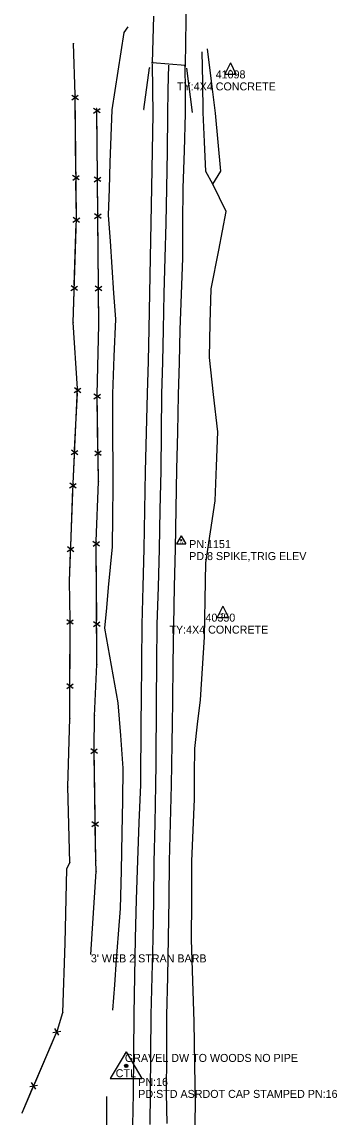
# Model space of a CAD drawing. Extents: x 1445297 to 1476720, y 2042269 to 2057889.
# Drawn here: x 1476144 to 1476341, y 2054738 to 2055423 of the extents above; entities that cross this region are included whole.
import ezdxf

# ---------------------------------------------------------------- set-up
doc = ezdxf.new("R2010")
doc.units = 0
for name, color, linetype in [('S_BRIDGE', 7, 'Continuous'), ('S_DITCHLINE', 7, 'Continuous'), ('S_EDGE_PAVEMENT', 7, 'Continuous'), ('S_EXIST_ROW', 7, 'Continuous'), ('S_EXIST_ROW_ANNOT', 7, 'Continuous'), ('S_FENCE', 7, 'Continuous'), ('S_FENCE_ANNOT', 7, 'Continuous'), ('S_GUARDRAIL', 7, 'Continuous'), ('S_MSC_PT_SYM', 7, 'Continuous'), ('S_PAVEMENT_CROWN', 7, 'Continuous'), ('S_PRIMARY_CTL', 7, 'Continuous'), ('S_PRIMARY_CTL_ANNOT', 7, 'Continuous'), ('S_RDW_PT_SYM', 7, 'Continuous'), ('S_SECONDARY_CTL', 7, 'Continuous'), ('S_SECONDARY_CTL_ANNOT', 7, 'Continuous'), ('S_STR_PT_SYM', 7, 'Continuous'), ('S_SURVEY_TEXT_ANNOT', 7, 'Continuous')]:
    doc.layers.add(name, color=color, linetype=linetype)

msp = doc.modelspace()

# ---------------------------------------------------------------- linework, layer by layer
at = {"layer": 'S_BRIDGE'}
for p, q in [((1476247.02, 2055440.81), (1476246.16, 2055395.44)), ((1476225.79, 2055397.26), (1476226.59, 2055426.32)), ((1476246.16, 2055395.44), (1476225.79, 2055397.26))]:
    msp.add_line(p, q, dxfattribs=at)
at = {"layer": 'S_DITCHLINE'}
for points in [[(1476201, 2054805.2), (1476202.23, 2054821.06), (1476203.47, 2054836.92), (1476204.7, 2054852.77), (1476205.93, 2054868.63), (1476206.4, 2054892.32), (1476206.86, 2054916.02), (1476207.23, 2054936.26), (1476207.6, 2054956.5), (1476206.03, 2054976.84), (1476204.47, 2054997.17), (1476200.28, 2055020.49), (1476196.1, 2055043.8), (1476197.27, 2055056.53), (1476198.44, 2055069.26), (1476199.61, 2055081.99), (1476200.78, 2055094.72), (1476201.04, 2055113.61), (1476201.3, 2055132.51), (1476201.24, 2055146.94), (1476201.18, 2055161.38), (1476201.12, 2055175.82), (1476201.06, 2055190.26), (1476201.98, 2055213.68), (1476202.9, 2055237.09), (1476201.79, 2055253.31), (1476200.68, 2055269.53), (1476199.56, 2055285.75), (1476198.45, 2055301.96), (1476198.98, 2055318.41), (1476199.5, 2055334.85), (1476200.03, 2055351.3), (1476200.56, 2055367.75), (1476204.33, 2055391.96), (1476208.11, 2055416.17), (1476210.63, 2055419.7)], [(1476252.3, 2054729.43), (1476252.65, 2054745), (1476252.47, 2054758.22), (1476252.3, 2054771.45), (1476252.13, 2054784.67), (1476251.95, 2054797.89), (1476251.51, 2054810.74), (1476251.06, 2054823.59), (1476250.62, 2054836.44), (1476250.17, 2054849.29), (1476250.32, 2054873.74), (1476250.48, 2054898.19), (1476251.24, 2054917.57), (1476252, 2054936.94), (1476252.11, 2054952.82), (1476252.22, 2054968.69), (1476254.04, 2054983.85), (1476255.87, 2054999.01), (1476257.11, 2055018.63), (1476258.35, 2055038.25), (1476258.8, 2055061.52), (1476259.25, 2055084.79), (1476262.13, 2055104.11), (1476265.01, 2055123.44), (1476265.87, 2055145.03), (1476266.73, 2055166.61), (1476264.05, 2055189.83), (1476261.37, 2055213.04), (1476261.96, 2055234.47), (1476262.55, 2055255.9), (1476267.2, 2055280.06), (1476271.86, 2055304.23), (1476263.53, 2055321.44), (1476259.16, 2055329.3), (1476258.37, 2055347.74), (1476257.58, 2055366.18), (1476257.21, 2055385.09), (1476256.83, 2055404.01)], [(1476263.53, 2055321.44), (1476268.63, 2055329.52), (1476266.91, 2055347.57), (1476265.19, 2055365.63), (1476262.72, 2055385.73), (1476260.25, 2055405.83)], [(1476197.26, 2054725.7), (1476197.33, 2054738.49), (1476197.4, 2054751.28)]]:
    msp.add_lwpolyline(points, dxfattribs=at)
at = {"layer": 'S_EDGE_PAVEMENT'}
for points in [[(1476213.56, 2054733.17), (1476213.95, 2054753.04), (1476214.18, 2054777.82), (1476214.4, 2054802.6), (1476214.8, 2054826.33), (1476215.19, 2054850.05), (1476215.94, 2054874.34), (1476216.69, 2054898.63), (1476217.6, 2054922.36), (1476218.51, 2054946.09), (1476218.63, 2054959.26), (1476218.75, 2054972.43), (1476218.87, 2054985.59), (1476218.99, 2054998.76), (1476219.22, 2055022.5), (1476219.45, 2055046.25), (1476220.09, 2055069.87), (1476220.73, 2055093.49), (1476221.13, 2055117.66), (1476221.53, 2055141.83), (1476222.13, 2055166.13), (1476222.74, 2055190.44), (1476223.26, 2055210.74), (1476223.77, 2055231.04), (1476224.21, 2055253.15), (1476224.65, 2055275.26), (1476225.05, 2055297.22), (1476225.45, 2055319.18), (1476225.88, 2055342.1), (1476226.32, 2055365.01), (1476226.04, 2055380.65), (1476225.76, 2055396.29)], [(1476234.92, 2054734.25), (1476234.56, 2054753.27), (1476234.73, 2054777.57), (1476234.9, 2054801.86), (1476235.36, 2054826.08), (1476235.82, 2054850.3), (1476236.19, 2054874.28), (1476236.56, 2054898.27), (1476237.18, 2054922), (1476237.79, 2054945.73), (1476237.98, 2054958.72), (1476238.16, 2054971.7), (1476238.34, 2054984.68), (1476238.52, 2054997.67), (1476238.8, 2055021.72), (1476239.08, 2055045.77), (1476239.6, 2055069.72), (1476240.13, 2055093.67), (1476240.62, 2055118.48), (1476241.12, 2055143.29), (1476241.64, 2055166.45), (1476242.16, 2055189.61), (1476242.7, 2055209.96), (1476243.23, 2055230.31), (1476243.98, 2055252.69), (1476244.73, 2055275.07), (1476244.87, 2055297.04), (1476245.02, 2055319.02), (1476245.79, 2055342.27), (1476246.55, 2055365.52), (1476246.38, 2055380.12), (1476246.22, 2055394.73)]]:
    msp.add_lwpolyline(points, dxfattribs=at)
at = {"layer": 'S_EXIST_ROW'}
for p, q in [((1476274.51, 2055397.17), (1476270.98, 2055390.08)), ((1476274.51, 2055397.17), (1476277.99, 2055390.08)), ((1476270.98, 2055390.08), (1476277.99, 2055390.08)), ((1476274.49, 2055392.45), (1476274.49, 2055392.45)), ((1476269.76, 2055057.71), (1476266.24, 2055050.62)), ((1476269.76, 2055057.71), (1476273.25, 2055050.62)), ((1476266.24, 2055050.62), (1476273.25, 2055050.62)), ((1476269.75, 2055052.98), (1476269.75, 2055052.98))]:
    msp.add_line(p, q, dxfattribs=at)
for centre, radius in [((1476274.49, 2055392.45), 0.12), ((1476274.49, 2055392.45), 0.06), ((1476269.75, 2055052.98), 0.12), ((1476269.75, 2055052.98), 0.06)]:
    msp.add_circle(centre, radius, dxfattribs=at)
at = {"layer": 'S_FENCE'}
for p, q in [((1476177.47, 2055377.08), (1476176.56, 2055409.33)), ((1476179.55, 2055374.04), (1476175.42, 2055376.86)), ((1476175.46, 2055373.99), (1476179.52, 2055376.91)), ((1476178.33, 2055300.34), (1476177.47, 2055377.08)), ((1476193.1, 2055365.85), (1476188.97, 2055368.67)), ((1476189, 2055365.81), (1476193.07, 2055368.72)), ((1476191.74, 2055302.89), (1476191.02, 2055368.66)), ((1476180.11, 2055323.97), (1476175.98, 2055326.79)), ((1476176.02, 2055323.92), (1476180.08, 2055326.83)), ((1476193.57, 2055322.94), (1476189.44, 2055325.76)), ((1476189.47, 2055322.89), (1476193.54, 2055325.8)), ((1476176.19, 2055297.58), (1476180.38, 2055300.32)), ((1476180.29, 2055297.45), (1476176.28, 2055300.45)), ((1476176.31, 2055235), (1476178.33, 2055300.34)), ((1476193.81, 2055300), (1476189.69, 2055302.83)), ((1476189.72, 2055299.96), (1476193.79, 2055302.87)), ((1476192.36, 2055233.5), (1476191.74, 2055302.89)), ((1476174.87, 2055254.95), (1476179.06, 2055257.69)), ((1476178.97, 2055254.82), (1476174.96, 2055257.82)), ((1476194.22, 2055254.73), (1476190.1, 2055257.56)), ((1476190.12, 2055254.69), (1476194.19, 2055257.59)), ((1476179.08, 2055193.74), (1476176.31, 2055235)), ((1476191.32, 2055189.9), (1476192.36, 2055233.5)), ((1476176.21, 2055134.24), (1476179.08, 2055193.74)), ((1476176.9, 2055191.14), (1476181.13, 2055193.81)), ((1476180.99, 2055190.95), (1476177.04, 2055194.01)), ((1476193.4, 2055187.33), (1476189.26, 2055190.14)), ((1476189.3, 2055187.28), (1476193.36, 2055190.2)), ((1476192.06, 2055135.4), (1476191.32, 2055189.9)), ((1476175.03, 2055152.32), (1476179.26, 2055154.98)), ((1476179.12, 2055152.12), (1476175.17, 2055155.18)), ((1476193.88, 2055151.77), (1476189.75, 2055154.59)), ((1476189.79, 2055151.72), (1476193.84, 2055154.64)), ((1476174.01, 2055073.26), (1476176.21, 2055134.24)), ((1476174.06, 2055131.58), (1476178.26, 2055134.3)), ((1476178.16, 2055131.43), (1476174.17, 2055134.45)), ((1476190.74, 2055098.18), (1476192.06, 2055135.4)), ((1476192.8, 2055095.12), (1476188.69, 2055097.96)), ((1476188.71, 2055095.1), (1476192.79, 2055097.98)), ((1476191.16, 2055021.29), (1476190.74, 2055098.18)), ((1476172.63, 2055091.8), (1476176.82, 2055094.51)), ((1476176.72, 2055091.65), (1476172.73, 2055094.66)), ((1476174.35, 2055049.05), (1476174.01, 2055073.26)), ((1476176.4, 2055046.32), (1476172.3, 2055049.15)), ((1476172.3, 2055046.33), (1476176.4, 2055049.15)), ((1476174.28, 2054987.57), (1476174.35, 2055049.05)), ((1476193.08, 2055044.96), (1476188.96, 2055047.8)), ((1476188.98, 2055044.94), (1476193.06, 2055047.82)), ((1476189.63, 2054989.2), (1476191.16, 2055021.29)), ((1476176.35, 2055006.21), (1476172.25, 2055009.04)), ((1476172.25, 2055006.22), (1476176.35, 2055009.04)), ((1476173, 2054944.65), (1476174.28, 2054987.57)), ((1476189.35, 2054968.52), (1476189.63, 2054989.2)), ((1476191.44, 2054965.63), (1476187.3, 2054968.44)), ((1476187.34, 2054965.57), (1476191.39, 2054968.5)), ((1476190.42, 2054898.61), (1476189.35, 2054968.52)), ((1476174.32, 2054897.52), (1476173, 2054944.65)), ((1476192.14, 2054920.02), (1476188, 2054922.82)), ((1476188.05, 2054919.96), (1476192.1, 2054922.89)), ((1476172.36, 2054893.51), (1476174.32, 2054897.52)), ((1476190.76, 2054891.75), (1476190.42, 2054898.61)), ((1476171.32, 2054847.03), (1476172.36, 2054893.51)), ((1476187.37, 2054840.04), (1476190.76, 2054891.75)), ((1476169.77, 2054803.8), (1476171.32, 2054847.03)), ((1476166.59, 2054792.73), (1476169.77, 2054803.8)), ((1476167.43, 2054789.5), (1476164.8, 2054793.75)), ((1476144.35, 2054741.03), (1476166.59, 2054792.73)), ((1476163.67, 2054791.12), (1476168.56, 2054792.13)), ((1476152.92, 2054755.77), (1476150.29, 2054760.02)), ((1476149.15, 2054757.39), (1476154.05, 2054758.4))]:
    msp.add_line(p, q, dxfattribs=at)
for points in [[(1476177.47, 2055377.08), (1476176.56, 2055409.33)], [(1476178.02, 2055327.65), (1476177.51, 2055373.17)], [(1476191.48, 2055326.3), (1476191.06, 2055365.31)], [(1476178.33, 2055300.34), (1476178.07, 2055323.1)], [(1476191.74, 2055302.89), (1476191.52, 2055322.4)], [(1476177.03, 2055258.26), (1476178.22, 2055297.01)], [(1476192.14, 2055258.2), (1476191.77, 2055299.36)], [(1476176.31, 2055235), (1476176.91, 2055254.38)], [(1476192.36, 2055233.5), (1476192.18, 2055254.08)], [(1476179.08, 2055193.74), (1476176.31, 2055235)], [(1476191.32, 2055189.9), (1476192.36, 2055233.5)], [(1476177.23, 2055155.41), (1476178.93, 2055190.71)], [(1476191.79, 2055154.8), (1476191.35, 2055187.12)], [(1476176.21, 2055134.24), (1476177.06, 2055151.88)], [(1476192.06, 2055135.4), (1476191.84, 2055151.56)], [(1476174.79, 2055094.96), (1476176.09, 2055131.13)], [(1476190.74, 2055098.18), (1476192.06, 2055135.4)], [(1476174.01, 2055073.26), (1476174.66, 2055091.35)], [(1476191.01, 2055048.66), (1476190.76, 2055094.26)], [(1476174.35, 2055049.05), (1476174.01, 2055073.26)], [(1476174.3, 2055009.45), (1476174.35, 2055045.91)], [(1476191.16, 2055021.29), (1476191.03, 2055044.1)], [(1476189.63, 2054989.2), (1476191.16, 2055021.29)], [(1476174.28, 2054987.57), (1476174.3, 2055005.81)], [(1476173, 2054944.65), (1476174.28, 2054987.57)], [(1476189.35, 2054968.52), (1476189.63, 2054989.2)], [(1476190.04, 2054923.49), (1476189.4, 2054964.96)], [(1476174.32, 2054897.52), (1476173, 2054944.65)], [(1476190.42, 2054898.61), (1476190.1, 2054919.35)], [(1476172.36, 2054893.51), (1476174.32, 2054897.52)], [(1476190.76, 2054891.75), (1476190.42, 2054898.61)], [(1476171.32, 2054847.03), (1476172.36, 2054893.51)], [(1476187.37, 2054840.04), (1476190.76, 2054891.75)], [(1476169.77, 2054803.8), (1476171.32, 2054847.03)], [(1476166.59, 2054792.73), (1476169.77, 2054803.8)], [(1476152.26, 2054759.43), (1476165.45, 2054790.09)], [(1476144.35, 2054741.03), (1476150.94, 2054756.36)]]:
    msp.add_lwpolyline(points, dxfattribs=at)
at = {"layer": 'S_GUARDRAIL'}
for p, q in [((1476220.54, 2055367.98), (1476223.91, 2055393.97)), ((1476250.86, 2055366.18), (1476247.3, 2055393.89))]:
    msp.add_line(p, q, dxfattribs=at)
at = {"layer": 'S_MSC_PT_SYM'}
for points in [[(1476176.56, 2055409.33), (1476176.56, 2055409.38), (1476176.56, 2055409.33), (1476176.51, 2055409.33), (1476176.56, 2055409.33), (1476176.56, 2055409.28), (1476176.56, 2055409.33), (1476176.61, 2055409.33)], [(1476177.47, 2055377.08), (1476177.47, 2055377.13), (1476177.47, 2055377.08), (1476177.42, 2055377.08), (1476177.47, 2055377.08), (1476177.47, 2055377.03), (1476177.47, 2055377.08), (1476177.52, 2055377.08)], [(1476191.02, 2055368.66), (1476191.02, 2055368.71), (1476191.02, 2055368.66), (1476190.97, 2055368.66), (1476191.02, 2055368.66), (1476191.02, 2055368.61), (1476191.02, 2055368.66), (1476191.07, 2055368.66)], [(1476178.33, 2055300.34), (1476178.33, 2055300.39), (1476178.33, 2055300.34), (1476178.28, 2055300.34), (1476178.33, 2055300.34), (1476178.33, 2055300.29), (1476178.33, 2055300.34), (1476178.38, 2055300.34)], [(1476191.74, 2055302.89), (1476191.74, 2055302.94), (1476191.74, 2055302.89), (1476191.69, 2055302.89), (1476191.74, 2055302.89), (1476191.74, 2055302.84), (1476191.74, 2055302.89), (1476191.79, 2055302.89)], [(1476176.31, 2055235), (1476176.31, 2055235.05), (1476176.31, 2055235), (1476176.26, 2055235), (1476176.31, 2055235), (1476176.31, 2055234.95), (1476176.31, 2055235), (1476176.36, 2055235)], [(1476192.36, 2055233.5), (1476192.36, 2055233.55), (1476192.36, 2055233.5), (1476192.31, 2055233.5), (1476192.36, 2055233.5), (1476192.36, 2055233.45), (1476192.36, 2055233.5), (1476192.41, 2055233.5)], [(1476179.08, 2055193.74), (1476179.08, 2055193.79), (1476179.08, 2055193.74), (1476179.03, 2055193.74), (1476179.08, 2055193.74), (1476179.08, 2055193.69), (1476179.08, 2055193.74), (1476179.13, 2055193.74)], [(1476191.32, 2055189.9), (1476191.32, 2055189.95), (1476191.32, 2055189.9), (1476191.27, 2055189.9), (1476191.32, 2055189.9), (1476191.32, 2055189.85), (1476191.32, 2055189.9), (1476191.37, 2055189.9)], [(1476176.21, 2055134.24), (1476176.21, 2055134.29), (1476176.21, 2055134.24), (1476176.16, 2055134.24), (1476176.21, 2055134.24), (1476176.21, 2055134.19), (1476176.21, 2055134.24), (1476176.26, 2055134.24)], [(1476192.06, 2055135.4), (1476192.06, 2055135.45), (1476192.06, 2055135.4), (1476192.01, 2055135.4), (1476192.06, 2055135.4), (1476192.06, 2055135.35), (1476192.06, 2055135.4), (1476192.11, 2055135.4)], [(1476190.74, 2055098.18), (1476190.74, 2055098.23), (1476190.74, 2055098.18), (1476190.69, 2055098.18), (1476190.74, 2055098.18), (1476190.74, 2055098.13), (1476190.74, 2055098.18), (1476190.79, 2055098.18)], [(1476174.01, 2055073.26), (1476174.01, 2055073.31), (1476174.01, 2055073.26), (1476173.96, 2055073.26), (1476174.01, 2055073.26), (1476174.01, 2055073.21), (1476174.01, 2055073.26), (1476174.06, 2055073.26)], [(1476174.35, 2055049.05), (1476174.35, 2055049.1), (1476174.35, 2055049.05), (1476174.3, 2055049.05), (1476174.35, 2055049.05), (1476174.35, 2055049), (1476174.35, 2055049.05), (1476174.4, 2055049.05)], [(1476191.16, 2055021.29), (1476191.16, 2055021.34), (1476191.16, 2055021.29), (1476191.11, 2055021.29), (1476191.16, 2055021.29), (1476191.16, 2055021.24), (1476191.16, 2055021.29), (1476191.21, 2055021.29)], [(1476174.28, 2054987.57), (1476174.28, 2054987.62), (1476174.28, 2054987.57), (1476174.23, 2054987.57), (1476174.28, 2054987.57), (1476174.28, 2054987.52), (1476174.28, 2054987.57), (1476174.33, 2054987.57)], [(1476189.63, 2054989.2), (1476189.63, 2054989.25), (1476189.63, 2054989.2), (1476189.58, 2054989.2), (1476189.63, 2054989.2), (1476189.63, 2054989.15), (1476189.63, 2054989.2), (1476189.68, 2054989.2)], [(1476189.35, 2054968.52), (1476189.35, 2054968.57), (1476189.35, 2054968.52), (1476189.3, 2054968.52), (1476189.35, 2054968.52), (1476189.35, 2054968.47), (1476189.35, 2054968.52), (1476189.4, 2054968.52)], [(1476173, 2054944.65), (1476173, 2054944.7), (1476173, 2054944.65), (1476172.95, 2054944.65), (1476173, 2054944.65), (1476173, 2054944.6), (1476173, 2054944.65), (1476173.05, 2054944.65)], [(1476174.32, 2054897.52), (1476174.32, 2054897.57), (1476174.32, 2054897.52), (1476174.27, 2054897.52), (1476174.32, 2054897.52), (1476174.32, 2054897.47), (1476174.32, 2054897.52), (1476174.37, 2054897.52)], [(1476190.42, 2054898.61), (1476190.42, 2054898.66), (1476190.42, 2054898.61), (1476190.37, 2054898.61), (1476190.42, 2054898.61), (1476190.42, 2054898.56), (1476190.42, 2054898.61), (1476190.47, 2054898.61)], [(1476172.36, 2054893.51), (1476172.36, 2054893.56), (1476172.36, 2054893.51), (1476172.31, 2054893.51), (1476172.36, 2054893.51), (1476172.36, 2054893.46), (1476172.36, 2054893.51), (1476172.41, 2054893.51)], [(1476190.76, 2054891.75), (1476190.76, 2054891.8), (1476190.76, 2054891.75), (1476190.71, 2054891.75), (1476190.76, 2054891.75), (1476190.76, 2054891.7), (1476190.76, 2054891.75), (1476190.81, 2054891.75)], [(1476171.32, 2054847.03), (1476171.32, 2054847.08), (1476171.32, 2054847.03), (1476171.27, 2054847.03), (1476171.32, 2054847.03), (1476171.32, 2054846.98), (1476171.32, 2054847.03), (1476171.37, 2054847.03)], [(1476187.37, 2054840.04), (1476187.37, 2054840.09), (1476187.37, 2054840.04), (1476187.32, 2054840.04), (1476187.37, 2054840.04), (1476187.37, 2054839.99), (1476187.37, 2054840.04), (1476187.42, 2054840.04)], [(1476169.77, 2054803.8), (1476169.77, 2054803.85), (1476169.77, 2054803.8), (1476169.72, 2054803.8), (1476169.77, 2054803.8), (1476169.77, 2054803.75), (1476169.77, 2054803.8), (1476169.82, 2054803.8)], [(1476166.59, 2054792.73), (1476166.59, 2054792.78), (1476166.59, 2054792.73), (1476166.54, 2054792.73), (1476166.59, 2054792.73), (1476166.59, 2054792.68), (1476166.59, 2054792.73), (1476166.64, 2054792.73)], [(1476208.61, 2054777.83), (1476208.61, 2054777.88), (1476208.61, 2054777.83), (1476208.56, 2054777.83), (1476208.61, 2054777.83), (1476208.61, 2054777.78), (1476208.61, 2054777.83), (1476208.66, 2054777.83)], [(1476144.35, 2054741.03), (1476144.35, 2054741.08), (1476144.35, 2054741.03), (1476144.3, 2054741.03), (1476144.35, 2054741.03), (1476144.35, 2054740.98), (1476144.35, 2054741.03), (1476144.4, 2054741.03)]]:
    msp.add_lwpolyline(points, dxfattribs=at)
at = {"layer": 'S_PAVEMENT_CROWN'}
msp.add_lwpolyline([(1476224.32, 2054733.72), (1476224.58, 2054753.41), (1476224.75, 2054777.87), (1476224.93, 2054802.33), (1476225.55, 2054826.04), (1476226.17, 2054849.75), (1476226.58, 2054873.68), (1476226.99, 2054897.61), (1476227.47, 2054921.8), (1476227.94, 2054945.98), (1476228.05, 2054959.01), (1476228.16, 2054972.05), (1476228.27, 2054985.08), (1476228.37, 2054998.11), (1476228.61, 2055022.12), (1476228.85, 2055046.13), (1476229.55, 2055069.7), (1476230.25, 2055093.28), (1476230.72, 2055117.76), (1476231.18, 2055142.24), (1476231.48, 2055166.17), (1476231.78, 2055190.1), (1476232.27, 2055210.36), (1476232.76, 2055230.63), (1476233.22, 2055253), (1476233.68, 2055275.37), (1476234.29, 2055297.07), (1476234.89, 2055318.77), (1476235.12, 2055341.86), (1476235.34, 2055364.96), (1476235.73, 2055380.35), (1476236.13, 2055395.75)], dxfattribs=at)
at = {"layer": 'S_PRIMARY_CTL'}
for p, q in [((1476209.46, 2054779.04), (1476199.43, 2054762.52)), ((1476209.46, 2054779.04), (1476219.29, 2054762.52)), ((1476199.43, 2054762.52), (1476219.29, 2054762.52))]:
    msp.add_line(p, q, dxfattribs=at)
for radius in [1.04, 0.609, 0.344]:
    msp.add_circle((1476209.46, 2054770.34), radius, dxfattribs=at)
at = {"layer": 'S_RDW_PT_SYM'}
for points in [[(1476223.91, 2055393.97), (1476223.91, 2055394.02), (1476223.91, 2055393.97), (1476223.86, 2055393.97), (1476223.91, 2055393.97), (1476223.91, 2055393.92), (1476223.91, 2055393.97), (1476223.96, 2055393.97)], [(1476247.3, 2055393.89), (1476247.3, 2055393.94), (1476247.3, 2055393.89), (1476247.25, 2055393.89), (1476247.3, 2055393.89), (1476247.3, 2055393.84), (1476247.3, 2055393.89), (1476247.35, 2055393.89)], [(1476220.54, 2055367.98), (1476220.54, 2055368.03), (1476220.54, 2055367.98), (1476220.49, 2055367.98), (1476220.54, 2055367.98), (1476220.54, 2055367.93), (1476220.54, 2055367.98), (1476220.59, 2055367.98)], [(1476250.86, 2055366.18), (1476250.86, 2055366.23), (1476250.86, 2055366.18), (1476250.81, 2055366.18), (1476250.86, 2055366.18), (1476250.86, 2055366.13), (1476250.86, 2055366.18), (1476250.91, 2055366.18)]]:
    msp.add_lwpolyline(points, dxfattribs=at)
at = {"layer": 'S_SECONDARY_CTL'}
for p, q in [((1476243.76, 2055101.55), (1476240.75, 2055096.6)), ((1476240.75, 2055096.6), (1476246.7, 2055096.6)), ((1476243.76, 2055101.55), (1476246.7, 2055096.6))]:
    msp.add_line(p, q, dxfattribs=at)
for radius in [0.311, 0.183, 0.103]:
    msp.add_circle((1476243.76, 2055098.94), radius, dxfattribs=at)
at = {"layer": 'S_STR_PT_SYM'}
for points in [[(1476225.79, 2055397.26), (1476225.79, 2055397.76), (1476225.79, 2055397.26), (1476225.29, 2055397.26), (1476225.79, 2055397.26), (1476225.79, 2055396.76), (1476225.79, 2055397.26), (1476226.29, 2055397.26)], [(1476246.16, 2055395.44), (1476246.16, 2055395.94), (1476246.16, 2055395.44), (1476245.66, 2055395.44), (1476246.16, 2055395.44), (1476246.16, 2055394.94), (1476246.16, 2055395.44), (1476246.66, 2055395.44)]]:
    msp.add_lwpolyline(points, dxfattribs=at)

# ---------------------------------------------------------------- texts
at = {"layer": 'S_EXIST_ROW_ANNOT'}
for s, p in [('41098', (1476265.32, 2055387.45)), ('TY:4X4 CONCRETE', (1476241.19, 2055379.95)), ('40350', (1476258.94, 2055047.98)), ('TY:4X4 CONCRETE', (1476236.44, 2055040.48))]:
    msp.add_text(s, height=5, dxfattribs=at).set_placement(p)
at = {"layer": 'S_FENCE_ANNOT'}
msp.add_text("3' WEB 2 STRAN BARB", height=5, dxfattribs=at).set_placement((1476187.37, 2054835.04))
at = {"layer": 'S_PRIMARY_CTL'}
msp.add_text('CTL', height=5, dxfattribs=at).set_placement((1476202.88, 2054763.26))
at = {"layer": 'S_PRIMARY_CTL_ANNOT'}
for s, p in [('PN:16', (1476216.96, 2054757.84)), ('PD:STD ASRDOT CAP STAMPED PN:16', (1476216.96, 2054750.34))]:
    msp.add_text(s, height=5, dxfattribs=at).set_placement(p)
at = {"layer": 'S_SECONDARY_CTL'}
msp.add_text('TV', height=1.5, dxfattribs=at).set_placement((1476242.55, 2055096.93))
at = {"layer": 'S_SECONDARY_CTL_ANNOT'}
for s, p in [('PN:1151', (1476248.76, 2055093.94)), ('PD:8 SPIKE,TRIG ELEV', (1476248.76, 2055086.44))]:
    msp.add_text(s, height=5, dxfattribs=at).set_placement(p)
at = {"layer": 'S_SURVEY_TEXT_ANNOT'}
msp.add_text('GRAVEL DW TO WOODS NO PIPE', height=5, dxfattribs=at).set_placement((1476208.61, 2054772.83))

doc.saveas('drawing.dxf')
